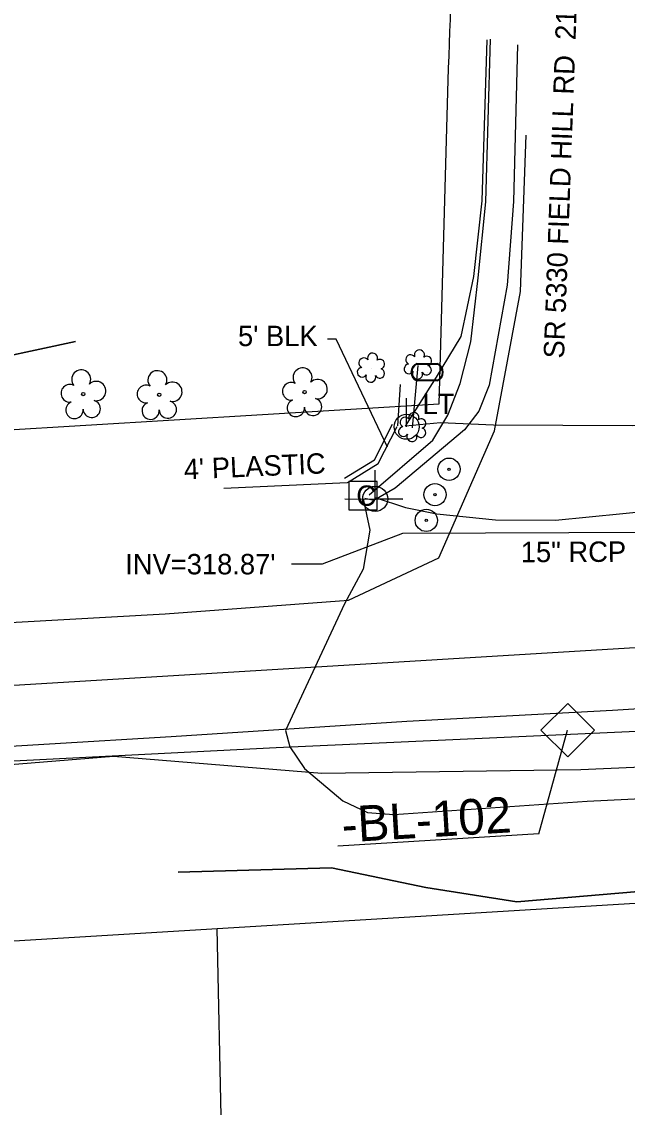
# Model space of a CAD drawing. Extents: x 2110969 to 2113691, y 670003 to 672285.
# Drawn here: x 2111867.6 to 2111986.2, y 670375.7 to 670588.4 of the extents above; entities that cross this region are included whole.
import ezdxf

# ---------------------------------------------------------------- set-up
doc = ezdxf.new("R2010")
doc.units = 0
for name, color, linetype in [('Default', 7, 'Continuous'), ('Exist Building', 7, 'Continuous'), ('Exist Building Leader', 7, 'Continuous'), ('Exist Building Text', 7, 'Continuous'), ('Exist Horizontal Alignment', 7, 'Continuous'), ('Exist Horizontal Baseline Alignment Station Label', 7, 'Continuous'), ('Exist Other Culture Anchor (Guy Wire) CELL', 7, 'Continuous'), ('Exist Other Culture Fence Line', 7, 'Continuous'), ('Exist Other Culture Fence Line Text', 7, 'Continuous'), ('Exist Property Line', 7, 'Continuous'), ('Exist Right of Way Line', 7, 'Continuous'), ('Exist Roads EOP', 7, 'Continuous'), ('Exist Roads EOP Text', 7, 'Continuous'), ('Exist Structure Minor Pipes RCP 15 Inch', 7, 'Continuous'), ('Exist Structure Minor Pipes RCP 15 Inch Invert', 7, 'Continuous'), ('Exist Structure Minor Pipes RCP 15 Inch Leader', 7, 'Continuous'), ('Exist Structure Minor Pipes RCP 15 Inch Text', 7, 'Continuous'), ('Exist Utilities Power Joint Use Telephone CELL', 7, 'Continuous'), ('Exist Utilities Power Pole CELL', 7, 'Continuous'), ('Exist Utilities Power Pole Text', 7, 'Continuous'), ('Exist Utilities Power UG Cable SUE LOS B', 7, 'Continuous'), ('Exist Utilities Telephone UG FO SUE LOS B', 7, 'Continuous'), ('Exist Utilities TV Pedestal CELL', 7, 'Continuous'), ('Exist Utilities TV UG Cable SUE LOS B', 7, 'Continuous'), ('Exist Utilities TV UG FO Cable SUE LOS B', 7, 'Continuous'), ('Exist Utilities Water Meter CELL', 7, 'Continuous'), ('Exist Utilities Water UG Line SUE LOS C', 7, 'Continuous'), ('Exist Vegetation Hedge Row', 7, 'Continuous'), ('Exist Vegetation Shrub CELL', 7, 'Continuous'), ('Exist Vegetation Tree CELL', 7, 'Continuous')]:
    doc.layers.add(name, color=color, linetype=linetype)

msp = doc.modelspace()

# ---------------------------------------------------------------- linework, layer by layer
at = {"layer": 'Default'}
for centre, radius in [((2111951.3, 670500.76), 2.18), ((2111951.3, 670500.76), 0.24), ((2111946.84, 670490.73), 2.18), ((2111946.84, 670490.73), 0.24)]:
    msp.add_circle(centre, radius, dxfattribs=at)
at = {"layer": 'Exist Building'}
for points in [[(2111930.86, 670499.01), (2111936.68, 670502.57), (2111940.25, 670509.6)], [(2111931.39, 670498.15), (2111937.44, 670501.87), (2111941.14, 670509.15)]]:
    msp.add_lwpolyline(points, dxfattribs=at)
at = {"layer": 'Exist Building Leader'}
msp.add_lwpolyline([(2111939.23, 670505.07), (2111929.22, 670526.23), (2111927.53, 670526.23)], dxfattribs=at)
at = {"layer": 'Exist Horizontal Alignment'}
msp.add_line((2111597.13, 670442.15), (2113362.13, 670549.12), dxfattribs=at)
at = {"layer": 'Exist Horizontal Baseline Alignment Station Label'}
for p, q in [((2111968.9, 670429.32), (2111974.52, 670449.62)), ((2111974.52, 670449.62), (2111974.52, 670449.62)), ((2111968.9, 670429.32), (2111929.5, 670426.93))]:
    msp.add_line(p, q, dxfattribs=at)
msp.add_lwpolyline([(2111969.3, 670449.63), (2111974.55, 670454.88), (2111979.8, 670449.62), (2111974.55, 670444.38)], close=True, dxfattribs=at)
at = {"layer": 'Exist Other Culture Anchor (Guy Wire) CELL'}
for radius in [2.18, 0.24]:
    msp.add_circle((2111948.55, 670495.79), radius, dxfattribs=at)
at = {"layer": 'Exist Other Culture Fence Line'}
for p, q in [((2111941.29, 670509.27), (2111941.82, 670517.39)), ((2111907.19, 670497.08), (2111931.35, 670498.14))]:
    msp.add_line(p, q, dxfattribs=at)
at = {"layer": 'Exist Property Line'}
msp.add_line((2111911.61, 670139.69), (2111905.91, 670410.77), dxfattribs=at)
at = {"layer": 'Exist Right of Way Line'}
for p, q in [((2111949.35, 670513.59), (2111951.11, 670576.98)), ((2111730.8, 670500.35), (2111949.35, 670513.59)), ((2111600.16, 670392.24), (2112086.29, 670421.71))]:
    msp.add_line(p, q, dxfattribs=at)
msp.add_arc((2112895.71, 670550.7), 944.98, 173.76908, 178.4087, dxfattribs=at)
at = {"layer": 'Exist Roads EOP'}
for points in [[(2111588.73, 670454.74), (2111643.53, 670457.25), (2111695.12, 670460.35), (2111747.76, 670463.95), (2111798.61, 670466.79), (2111847.8, 670469.72), (2111895.71, 670472.43), (2111931.59, 670475.09), (2111949.32, 670483.37), (2111960.18, 670508.31), (2111965.31, 670535.61), (2111966.42, 670566.2)], [(2111113.04, 670379.86), (2111152.42, 670385.43), (2111198.84, 670391.51), (2111251.82, 670398.21), (2111301.73, 670404.04), (2111354.14, 670410.05), (2111403.51, 670414.77), (2111454.4, 670419.12), (2111510.63, 670423.98), (2111568.62, 670427.85), (2111590.78, 670429.08), (2111644.59, 670432.49), (2111696.66, 670436.2), (2111749.46, 670439.16), (2111799.83, 670442.46), (2111849.2, 670445.5), (2111896.91, 670448.39), (2111943.04, 670451.41), (2111983.3, 670453.57), (2112026.46, 670456.2), (2112076.66, 670459.13), (2112122.85, 670461.54), (2112125.88, 670459.79)]]:
    msp.add_lwpolyline(points, dxfattribs=at)
at = {"layer": 'Exist Structure Minor Pipes RCP 15 Inch'}
msp.add_line((2112006.05, 670488.41), (2111942.19, 670488.15), dxfattribs=at)
at = {"layer": 'Exist Structure Minor Pipes RCP 15 Inch Leader'}
msp.add_lwpolyline([(2111942.19, 670488.15), (2111926.45, 670482.16), (2111920.45, 670482.16)], dxfattribs=at)
at = {"layer": 'Exist Utilities Power Joint Use Telephone CELL'}
msp.add_line((2111936.84, 670494.94), (2111936.84, 670494.94), dxfattribs=at)
msp.add_lwpolyline([(2111930.9, 670494.94), (2111942.24, 670494.91), (2111936.84, 670494.92), (2111936.84, 670500.57)], dxfattribs=at)
msp.add_circle((2111936.84, 670494.95), 2.45, dxfattribs=at)
at = {"layer": 'Exist Utilities Power Pole CELL'}
for q in [(2111943, 670514.69), (2111943, 670509.07)]:
    msp.add_line((2111943, 670509.07), q, dxfattribs=at)
msp.add_circle((2111943, 670509.07), 2.45, dxfattribs=at)
at = {"layer": 'Exist Utilities Power UG Cable SUE LOS B'}
for points in [[(2111935.64, 670495.72), (2111948.12, 670506.47), (2111951.05, 670511.32), (2111953.5, 670517.57), (2111955.56, 670525.75), (2111957.04, 670538.24), (2111958.54, 670553.16), (2111959.44, 670584.99)], [(2111935.64, 670495.72), (2111948.12, 670506.47), (2111951.05, 670511.32), (2111953.5, 670517.57), (2111955.56, 670525.75), (2111957.04, 670538.24), (2111958.54, 670553.16), (2111959.44, 670584.99)], [(2112007.37, 670510.88), (2111999.39, 670509.92), (2111987.16, 670509.26), (2111960, 670509.36), (2111949.61, 670509.83), (2111942.79, 670509.18), (2111948.87, 670518.77), (2111953.68, 670526.77), (2111956.13, 670538.52), (2111957.76, 670553.32), (2111958.76, 670584.91)], [(2112007.37, 670510.88), (2111999.39, 670509.92), (2111987.16, 670509.26), (2111960, 670509.36), (2111949.61, 670509.83), (2111942.79, 670509.18), (2111948.87, 670518.77), (2111953.68, 670526.77), (2111956.13, 670538.52), (2111957.76, 670553.32), (2111958.76, 670584.91)]]:
    msp.add_lwpolyline(points, dxfattribs=at)
at = {"layer": 'Exist Utilities Telephone UG FO SUE LOS B'}
msp.add_lwpolyline([(2111579.85, 670418.18), (2111631.45, 670423.41), (2111740.38, 670432.81), (2111885.62, 670444.53), (2111926.38, 670441.18), (2111977.11, 670441.9), (2112063.2, 670445.72), (2112109.68, 670453.08), (2112138.77, 670453.18), (2112237, 670457.87), (2112306.5, 670460.33), (2112380.27, 670463.6), (2112482.83, 670468.65), (2112529.94, 670475.11), (2112581.42, 670479.39), (2112613.55, 670486.14), (2112667.68, 670491.25), (2112816.71, 670501.11)], dxfattribs=at)
msp.add_lwpolyline([(2111579.85, 670418.18), (2111631.45, 670423.41), (2111740.38, 670432.81), (2111885.62, 670444.53), (2111926.38, 670441.18), (2111977.11, 670441.9), (2112063.2, 670445.72), (2112109.68, 670453.08), (2112138.77, 670453.18), (2112237, 670457.87), (2112306.5, 670460.33), (2112380.27, 670463.6), (2112482.83, 670468.65), (2112529.94, 670475.11), (2112581.42, 670479.39), (2112613.55, 670486.14), (2112667.68, 670491.25), (2112816.71, 670501.11)], dxfattribs=at)
at = {"layer": 'Exist Utilities TV Pedestal CELL'}
msp.add_line((2111934.45, 670495.58), (2111934.45, 670495.58), dxfattribs=at)
msp.add_line((2111934.45, 670495.58), (2111934.45, 670495.58), dxfattribs=at)
msp.add_lwpolyline([(2111931.67, 670492.81), (2111937.22, 670492.81), (2111937.22, 670498.36), (2111931.67, 670498.36), (2111931.67, 670492.81)], dxfattribs=at)
msp.add_lwpolyline([(2111931.67, 670492.81), (2111937.22, 670492.81), (2111937.22, 670498.36), (2111931.67, 670498.36), (2111931.67, 670492.81)], dxfattribs=at)
at = {"layer": 'Exist Utilities TV UG Cable SUE LOS B'}
for points in [[(2111964.68, 670583.93), (2111963.94, 670553.2), (2111962.71, 670536.84), (2111959.17, 670517.23), (2111957.14, 670512.15), (2111954.35, 670508.51), (2111940.75, 670497.08), (2111936.59, 670494.63), (2111934.81, 670495.02)], [(2111964.68, 670583.93), (2111963.94, 670553.2), (2111962.71, 670536.84), (2111959.17, 670517.23), (2111957.14, 670512.15), (2111954.35, 670508.51), (2111940.75, 670497.08), (2111936.59, 670494.63), (2111934.81, 670495.02)], [(2111934.48, 670494.95), (2111935.82, 670488.82), (2111934.5, 670481.19), (2111930.85, 670474.4), (2111919.31, 670449.55), (2111920.12, 670446.37), (2111923, 670442.15), (2111930.53, 670435.8), (2111935.36, 670433.48), (2111940.49, 670433.13), (2111978.37, 670435.75), (2112041.98, 670438.85), (2112095.74, 670443.8), (2112104.1, 670443.68), (2112117.77, 670442.27), (2112128.34, 670440.55), (2112140.14, 670436.6)], [(2111934.48, 670494.95), (2111935.82, 670488.82), (2111934.5, 670481.19), (2111930.85, 670474.4), (2111919.31, 670449.55), (2111920.12, 670446.37), (2111923, 670442.15), (2111930.53, 670435.8), (2111935.36, 670433.48), (2111940.49, 670433.13), (2111978.37, 670435.75), (2112041.98, 670438.85), (2112095.74, 670443.8), (2112104.1, 670443.68), (2112117.77, 670442.27), (2112128.34, 670440.55), (2112140.14, 670436.6)]]:
    msp.add_lwpolyline(points, dxfattribs=at)
at = {"layer": 'Exist Utilities TV UG FO Cable SUE LOS B'}
msp.add_lwpolyline([(2111936.85, 670495.19), (2111942.8, 670493.29), (2111948.9, 670492.04), (2111960.42, 670490.85), (2111972.12, 670490.75), (2111991.92, 670492.74), (2112005.47, 670495.02), (2112045.67, 670498.63), (2112084.03, 670500.97), (2112127.19, 670501.84), (2112167.43, 670504.61), (2112208.93, 670510.16), (2112249.37, 670516.92), (2112286.91, 670525.52), (2112332.02, 670532.67), (2112360.55, 670534.37), (2112382.17, 670531.42), (2112408.52, 670528.19), (2112425.77, 670527.19), (2112444.78, 670526.78), (2112451.38, 670527.68), (2112454.55, 670529.63), (2112455.41, 670531.77)], dxfattribs=at)
msp.add_lwpolyline([(2111936.85, 670495.19), (2111942.8, 670493.29), (2111948.9, 670492.04), (2111960.42, 670490.85), (2111972.12, 670490.75), (2111991.92, 670492.74), (2112005.47, 670495.02), (2112045.67, 670498.63), (2112084.03, 670500.97), (2112127.19, 670501.84), (2112167.43, 670504.61), (2112208.93, 670510.16), (2112249.37, 670516.92), (2112286.91, 670525.52), (2112332.02, 670532.67), (2112360.55, 670534.37), (2112382.17, 670531.42), (2112408.52, 670528.19), (2112425.77, 670527.19), (2112444.78, 670526.78), (2112451.38, 670527.68), (2112454.55, 670529.63), (2112455.41, 670531.77)], dxfattribs=at)
at = {"layer": 'Exist Utilities Water Meter CELL'}
msp.add_line((2111947.02, 670519.76), (2111947.02, 670519.76), dxfattribs=at)
msp.add_line((2111947.02, 670519.76), (2111947.02, 670519.76), dxfattribs=at)
for points in [[(2111944.98, 670521.46), (2111949.06, 670521.46)], [(2111944.98, 670521.46), (2111949.06, 670521.46)], [(2111944.98, 670521.33), (2111949.06, 670521.33)], [(2111944.98, 670521.33), (2111949.06, 670521.33)], [(2111949.06, 670518.2), (2111944.96, 670518.2)], [(2111949.06, 670518.2), (2111944.96, 670518.2)], [(2111949.06, 670518.06), (2111944.96, 670518.06)], [(2111949.06, 670518.06), (2111944.96, 670518.06)]]:
    msp.add_lwpolyline(points, dxfattribs=at)
for centre, radius, start, end in [((2111945.71, 670519.76), 1.86, 113.178, 245.9794), ((2111945.71, 670519.76), 1.86, 113.178, 245.9794), ((2111945.72, 670519.76), 1.73, 115.3009, 243.7824), ((2111945.72, 670519.76), 1.73, 115.3009, 243.7824), ((2111948.31, 670519.77), 1.86, 293.6483, 66.3084), ((2111948.31, 670519.77), 1.86, 293.6483, 66.3084), ((2111948.32, 670519.76), 1.73, 295.1272, 64.8728), ((2111948.32, 670519.76), 1.73, 295.1272, 64.8728)]:
    msp.add_arc(centre, radius, start, end, dxfattribs=at)
at = {"layer": 'Exist Utilities Water UG Line SUE LOS C'}
msp.add_lwpolyline([(2111426.66, 670411.76), (2111552.37, 670422.8), (2111682.74, 670431.91), (2111812.01, 670440.88), (2111917.46, 670446.23), (2112062.93, 670452.85)], dxfattribs=at)
msp.add_lwpolyline([(2111426.66, 670411.76), (2111552.37, 670422.8), (2111682.74, 670431.91), (2111812.01, 670440.88), (2111917.46, 670446.23), (2112062.93, 670452.85)], dxfattribs=at)
at = {"layer": 'Exist Vegetation Hedge Row'}
for points in [[(2111878.14, 670525.76), (2111856.24, 670521.06), (2111814.71, 670526.8), (2111803.55, 670525.57)], [(2111803.55, 670525.57), (2111814.71, 670526.8), (2111856.24, 670521.06), (2111878.14, 670525.76)], [(2111898.25, 670421.79), (2111928.27, 670422.65), (2111946.74, 670418.82), (2111964.59, 670416), (2112011.48, 670419.96), (2112029.27, 670416.77), (2112034.8, 670419.02), (2112077.2, 670425.26), (2112115.55, 670419.48)], [(2112115.55, 670419.48), (2112077.2, 670425.26), (2112034.8, 670419.02), (2112029.27, 670416.77), (2112011.48, 670419.96), (2111964.59, 670416), (2111946.74, 670418.82), (2111928.27, 670422.65), (2111898.25, 670421.79)]]:
    msp.add_lwpolyline(points, dxfattribs=at)
at = {"layer": 'Exist Vegetation Shrub CELL'}
for p, q in [((2111944.17, 670508.84), (2111945.27, 670521.1)), ((2111945.27, 670521.1), (2111945.27, 670521.1)), ((2111936.09, 670520.48), (2111936.09, 670520.48)), ((2111944.17, 670508.84), (2111944.17, 670508.84))]:
    msp.add_line(p, q, dxfattribs=at)
for centre, radius, start, end in [((2111936.32, 670522.52), 0.99, 334.8391, 200.4717), ((2111943.79, 670522.22), 0.968, 35.8908, 245.4216), ((2111945.5, 670523.14), 0.99, 334.8391, 200.4717), ((2111934.61, 670521.6), 0.968, 35.8908, 245.4216), ((2111937.77, 670521.35), 0.929, 284.4567, 126.0861), ((2111943.47, 670520.39), 0.955, 95.1099, 327.9534), ((2111946.91, 670520.17), 0.937, 204.9913, 73.4601), ((2111946.95, 670521.96), 0.929, 284.4567, 126.0861), ((2111934.29, 670519.77), 0.955, 95.1099, 327.9534), ((2111935.97, 670518.79), 0.984, 151.2797, 21.387), ((2111937.73, 670519.55), 0.937, 204.9913, 73.4601), ((2111945.15, 670519.41), 0.984, 151.2797, 21.387), ((2111942.68, 670509.97), 0.968, 35.8908, 245.4216), ((2111944.4, 670510.88), 0.99, 334.8391, 200.4717), ((2111945.84, 670509.71), 0.929, 284.4567, 126.0861), ((2111942.37, 670508.14), 0.955, 95.1099, 327.9534), ((2111945.8, 670507.91), 0.937, 204.9913, 73.4601), ((2111944.04, 670507.16), 0.984, 151.2797, 21.387)]:
    msp.add_arc(centre, radius, start, end, dxfattribs=at)
at = {"layer": 'Exist Vegetation Tree CELL'}
for p, q in [((2111879.66, 670515.49), (2111879.66, 670515.49)), ((2111894.57, 670515.34), (2111894.57, 670515.34)), ((2111923.01, 670515.88), (2111923.01, 670515.88))]:
    msp.add_line(p, q, dxfattribs=at)
for centre in [(2111879.66, 670515.49), (2111894.57, 670515.34), (2111923.01, 670515.88)]:
    msp.add_circle(centre, 0.326, dxfattribs=at)
for centre, radius, start, end in [((2111879.27, 670518.36), 1.86, 330.1651, 219.7134), ((2111894.19, 670518.21), 1.86, 330.1651, 219.7134), ((2111922.62, 670518.75), 1.86, 330.1651, 219.7134), ((2111877.05, 670515.64), 1.73, 62.6636, 279.3457), ((2111882.21, 670516.08), 1.9, 257.1011, 134.1999), ((2111891.97, 670515.49), 1.73, 62.6636, 279.3457), ((2111897.12, 670515.93), 1.9, 257.1011, 134.1999), ((2111920.4, 670516.03), 1.73, 62.6636, 279.3457), ((2111925.56, 670516.46), 1.9, 257.1011, 134.1999), ((2111877.95, 670512.37), 1.69, 111.5671, 6.231), ((2111881.33, 670512.59), 1.7, 181.2822, 74.56), ((2111892.87, 670512.22), 1.69, 111.5671, 6.231), ((2111896.24, 670512.44), 1.7, 181.2822, 74.56), ((2111921.3, 670512.76), 1.69, 111.5671, 6.231), ((2111924.68, 670512.98), 1.7, 181.2822, 74.56)]:
    msp.add_arc(centre, radius, start, end, dxfattribs=at)

# ---------------------------------------------------------------- texts
at = {"layer": 'Exist Building Text'}
msp.add_text("5' BLK", height=4, dxfattribs=at).set_placement((2111909.98, 670524.88))
at = {"layer": 'Exist Horizontal Baseline Alignment Station Label'}
msp.add_text('-BL-102', height=7, rotation=3.4682, dxfattribs=at).set_placement((2111930.46, 670427.62))
at = {"layer": 'Exist Other Culture Fence Line Text'}
msp.add_text("4' PLASTIC", height=4, rotation=2.5193, dxfattribs=at).set_placement((2111899.46, 670498.74))
at = {"layer": 'Exist Roads EOP Text'}
msp.add_text("SR 5330 FIELD HILL RD  21' BST", height=4, rotation=87.9251, dxfattribs=at).set_placement((2111973.82, 670522.41))
at = {"layer": 'Exist Structure Minor Pipes RCP 15 Inch Invert'}
msp.add_text("INV=318.87'", height=4, dxfattribs=at).set_placement((2111887.9, 670480.16))
at = {"layer": 'Exist Structure Minor Pipes RCP 15 Inch Text'}
msp.add_text('15" RCP', height=4, rotation=0.2359, dxfattribs=at).set_placement((2111965.36, 670482.54))
at = {"layer": 'Exist Utilities Power Pole Text'}
msp.add_text('LT', height=4, dxfattribs=at).set_placement((2111946.12, 670511.55))
at = {"layer": 'Exist Utilities TV Pedestal CELL'}
msp.add_text('C', height=4, dxfattribs=at).set_placement((2111933.14, 670493.58))
msp.add_text('C', height=4, dxfattribs=at).set_placement((2111933.14, 670493.58))

doc.saveas('drawing.dxf')
